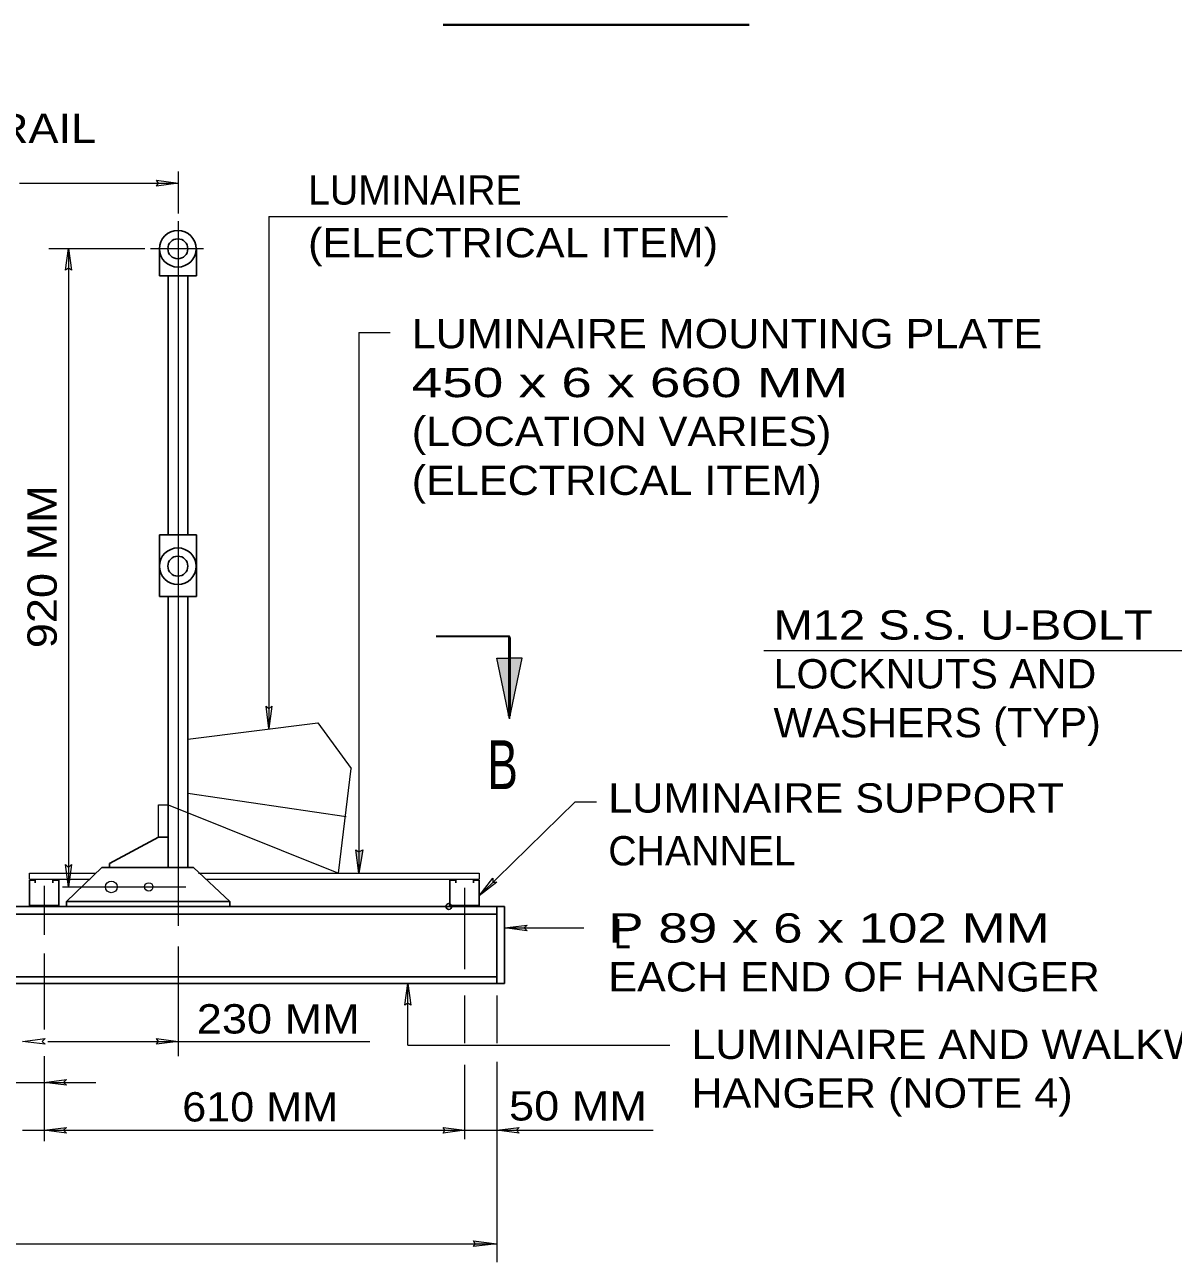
# Model space of a CAD drawing. Extents: x 312601.858 to 312602.699, y 144420.109 to 144420.704.
# Drawn here: x 312602.0438 to 312602.1613, y 144420.4578 to 144420.5844 of the extents above; entities that cross this region are included whole.
import ezdxf
from ezdxf.enums import TextEntityAlignment as Align

# ---------------------------------------------------------------- set-up
doc = ezdxf.new("R2010")
doc.units = 0
doc.header["$LTSCALE"] = 0.0012
doc.header["$PDMODE"] = 32
doc.header["$PDSIZE"] = 0.0006
doc.linetypes.add('DOT_DASHED', pattern=[7.7, 5, -1.2, 0.3, -1.2])
doc.linetypes.add('LONG_DASHED', pattern=[7.5, 6, -1.5])
for name, color, linetype, lineweight in [('1', 7, 'Continuous', 13), ('2', 7, 'Continuous', 13), ('39', 7, 'Continuous', 13), ('5', 7, 'Continuous', 25)]:
    doc.layers.add(name, color=color, linetype=linetype, lineweight=lineweight)

msp = doc.modelspace()

# ---------------------------------------------------------------- hatches: boundary and pattern name
at = {"layer": '1'}
for points in [[(312602.0921, 144420.5196), (312602.0934, 144420.5196), (312602.0934, 144420.5134)], [(312602.0921, 144420.5196), (312602.0934, 144420.5196), (312602.0934, 144420.5134)], [(312602.0947, 144420.5196), (312602.0934, 144420.5196), (312602.0934, 144420.5134)], [(312602.0947, 144420.5196), (312602.0934, 144420.5196), (312602.0934, 144420.5134)]]:
    msp.add_hatch(color=256, dxfattribs=at).paths.add_polyline_path(points)
at = {"layer": '39'}
for points in [[(312602.078, 144420.4998), (312602.0784, 144420.5), (312602.078, 144420.4976), (312602.0777, 144420.5)], [(312602.0899, 144420.4597), (312602.0897, 144420.46), (312602.0921, 144420.4597), (312602.0897, 144420.4594)]]:
    msp.add_hatch(color=256, dxfattribs=at).paths.add_polyline_path(points)

# ---------------------------------------------------------------- linework, layer by layer
at = {"layer": '1'}
for p, q in [((312602.0595, 144420.5694), (312602.0595, 144420.5651)), ((312602.0433, 144420.5682), (312602.0595, 144420.5682)), ((312602.0688, 144420.5648), (312602.1157, 144420.5648)), ((312602.0688, 144420.5648), (312602.0688, 144420.5124)), ((312602.0463, 144420.5615), (312602.0561, 144420.5615)), ((312602.0483, 144420.5615), (312602.0483, 144420.4962)), ((312602.078, 144420.5529), (312602.078, 144420.4976)), ((312602.078, 144420.5529), (312602.0812, 144420.5529)), ((312602.0935, 144420.5137), (312602.0935, 144420.5217)), ((312602.1194, 144420.5204), (312602.1734, 144420.5204)), ((312602.0903, 144420.4976), (312602.0903, 144420.497)), ((312602.0477, 144420.4962), (312602.0603, 144420.4962)), ((312602.0929, 144420.492), (312602.101, 144420.492)), ((312602.0595, 144420.4901), (312602.0595, 144420.4789)), ((312602.0458, 144420.4894), (312602.0458, 144420.4816)), ((312602.083, 144420.48), (312602.083, 144420.4863)), ((312602.0921, 144420.4851), (312602.0921, 144420.4802)), ((312602.0462, 144420.4804), (312602.0791, 144420.4804)), ((312602.083, 144420.48), (312602.1098, 144420.48)), ((312602.0458, 144420.4789), (312602.0458, 144420.4702)), ((312602.0921, 144420.4783), (312602.0921, 144420.4578)), ((312602.0888, 144420.478), (312602.0888, 144420.4704)), ((312602.0436, 144420.4713), (312602.0888, 144420.4713)), ((312601.967, 144420.4597), (312602.0921, 144420.4597))]:
    msp.add_line(p, q, dxfattribs=at)
at = {"layer": '1', "linetype": 'DOT_DASHED'}
for p, q in [((312602.0595, 144420.5643), (312602.0595, 144420.4922)), ((312602.0567, 144420.5615), (312602.0621, 144420.5615)), ((312602.0458, 144420.4963), (312602.0458, 144420.4913)), ((312602.0888, 144420.4961), (312602.0888, 144420.4878)), ((312602.0888, 144420.4851), (312602.0888, 144420.4802))]:
    msp.add_line(p, q, dxfattribs=at)
at = {"layer": '1', "lineweight": 25}
for p, q in [((312602.0576, 144420.5615), (312602.0576, 144420.5587)), ((312602.0614, 144420.5615), (312602.0614, 144420.5587)), ((312602.0576, 144420.5587), (312602.0614, 144420.5587)), ((312602.0585, 144420.5587), (312602.0585, 144420.5322)), ((312602.0605, 144420.5587), (312602.0605, 144420.5322)), ((312602.0576, 144420.5322), (312602.0614, 144420.5322)), ((312602.0576, 144420.5322), (312602.0576, 144420.5259)), ((312602.0614, 144420.5322), (312602.0614, 144420.5259)), ((312602.0576, 144420.5259), (312602.0614, 144420.5259)), ((312602.0585, 144420.5259), (312602.0585, 144420.4982)), ((312602.0605, 144420.5259), (312602.0605, 144420.4982)), ((312602.0525, 144420.4986), (312602.0575, 144420.5013)), ((312602.0575, 144420.5013), (312602.0585, 144420.5013)), ((312602.0525, 144420.4986), (312602.0525, 144420.4982)), ((312602.0517, 144420.4982), (312602.0481, 144420.4947)), ((312602.0517, 144420.4982), (312602.0611, 144420.4982)), ((312602.0648, 144420.4947), (312602.0611, 144420.4982)), ((312602.0481, 144420.4942), (312602.0481, 144420.4947)), ((312602.0481, 144420.4947), (312602.0648, 144420.4947)), ((312602.0648, 144420.4947), (312602.0648, 144420.4942)), ((312601.967, 144420.4934), (312602.0921, 144420.4934)), ((312601.9917, 144420.4942), (312602.0929, 144420.4942)), ((312602.0921, 144420.4942), (312602.0921, 144420.4863)), ((312602.0929, 144420.4942), (312602.0929, 144420.4863)), ((312602.0921, 144420.487), (312601.967, 144420.487)), ((312602.0929, 144420.4863), (312601.9662, 144420.4863))]:
    msp.add_line(p, q, dxfattribs=at)
at = {"layer": '1', "linetype": 'LONG_DASHED'}
for p, q in [((312602.0605, 144420.5113), (312602.0738, 144420.513)), ((312602.0738, 144420.513), (312602.0772, 144420.5083)), ((312602.0759, 144420.4976), (312602.0772, 144420.5083)), ((312602.0605, 144420.5058), (312602.0767, 144420.5034)), ((312602.0575, 144420.5013), (312602.0575, 144420.5046)), ((312602.0443, 144420.4976), (312602.0511, 144420.4976)), ((312602.0616, 144420.4976), (312602.0903, 144420.4976)), ((312602.0443, 144420.497), (312602.0505, 144420.497)), ((312602.0624, 144420.497), (312602.0903, 144420.497))]:
    msp.add_line(p, q, dxfattribs=at)
at = {"layer": '1'}
for points in [[(312602.0573, 144420.5685), (312602.0595, 144420.5682), (312602.0573, 144420.5679), (312602.0575, 144420.5682)], [(312602.048, 144420.5593), (312602.0483, 144420.5615), (312602.0486, 144420.5593), (312602.0483, 144420.5595)], [(312602.0921, 144420.5196), (312602.0934, 144420.5196), (312602.0934, 144420.5134)], [(312602.0921, 144420.5196), (312602.0934, 144420.5196), (312602.0934, 144420.5134)], [(312602.0947, 144420.5196), (312602.0934, 144420.5196), (312602.0934, 144420.5134)], [(312602.0947, 144420.5196), (312602.0934, 144420.5196), (312602.0934, 144420.5134)], [(312602.0691, 144420.5147), (312602.0688, 144420.5124), (312602.0685, 144420.5147), (312602.0688, 144420.5144)], [(312602.0486, 144420.4985), (312602.0483, 144420.4962), (312602.048, 144420.4985), (312602.0483, 144420.4982)], [(312602.0921, 144420.4967), (312602.0903, 144420.4953), (312602.0917, 144420.4971), (312602.0917, 144420.4967)], [(312602.0952, 144420.4917), (312602.0929, 144420.492), (312602.0952, 144420.4923), (312602.0949, 144420.492)], [(312602.0827, 144420.4841), (312602.083, 144420.4863), (312602.0833, 144420.4841), (312602.083, 144420.4843)], [(312602.0459, 144420.4801), (312602.0436, 144420.4804), (312602.0459, 144420.4807), (312602.0456, 144420.4804)], [(312602.0573, 144420.4807), (312602.0595, 144420.4804), (312602.0573, 144420.4801), (312602.0575, 144420.4804)], [(312602.0481, 144420.4759), (312602.0458, 144420.4762), (312602.0481, 144420.4765), (312602.0478, 144420.4762)], [(312602.0481, 144420.471), (312602.0458, 144420.4713), (312602.0481, 144420.4716), (312602.0478, 144420.4713)], [(312602.0866, 144420.4716), (312602.0888, 144420.4713), (312602.0866, 144420.471), (312602.0868, 144420.4713)], [(312602.0944, 144420.471), (312602.0921, 144420.4713), (312602.0944, 144420.4716), (312602.0941, 144420.4713)]]:
    msp.add_lwpolyline(points, close=True, dxfattribs=at)
at = {"layer": '1', "lineweight": 35}
msp.add_lwpolyline([(312602.0934, 144420.5196), (312602.0934, 144420.5218), (312602.0859, 144420.5218)], dxfattribs=at)
msp.add_lwpolyline([(312602.0934, 144420.5196), (312602.0934, 144420.5218), (312602.0859, 144420.5218)], dxfattribs=at)
at = {"layer": '1'}
for points in [[(312602.0933, 144420.5219), (312602.0933, 144420.5137), (312602.0935, 144420.5217)], [(312602.0905, 144420.4955), (312602.1001, 144420.5049), (312602.1023, 144420.5049)], [(312602.0268, 144420.4762), (312602.0436, 144420.4762), (312602.0458, 144420.4762), (312602.0511, 144420.4762)], [(312602.0888, 144420.4713), (312602.0921, 144420.4713), (312602.1081, 144420.4713)]]:
    msp.add_lwpolyline(points, dxfattribs=at)
at = {"layer": '1', "linetype": 'LONG_DASHED'}
msp.add_lwpolyline([(312602.0575, 144420.5046), (312602.0585, 144420.5046), (312602.0759, 144420.4976)], dxfattribs=at)
at = {"layer": '1', "lineweight": 25}
for centre, radius in [((312602.05948, 144420.56148), 0.00187), ((312602.05948, 144420.56148), 0.00102), ((312602.05948, 144420.52901), 0.00187), ((312602.05948, 144420.52901), 0.00102)]:
    msp.add_circle(centre, radius, dxfattribs=at)
at = {"layer": '1'}
for centre, radius in [((312602.05268, 144420.4962), 0.000595), ((312602.056505, 144420.4962), 0.000425)]:
    msp.add_circle(centre, radius, dxfattribs=at)
at = {"layer": '2', "lineweight": 40}
msp.add_line((312602.0866, 144420.5844), (312602.1179, 144420.5844), dxfattribs=at)
at = {"layer": '39'}
for points in [[(312602.078, 144420.4998), (312602.0784, 144420.5), (312602.078, 144420.4976), (312602.0777, 144420.5)], [(312602.0899, 144420.4597), (312602.0897, 144420.46), (312602.0921, 144420.4597), (312602.0897, 144420.4594)]]:
    msp.add_lwpolyline(points, close=True, dxfattribs=at)
at = {"layer": '5', "lineweight": 13}
for p, q in [((312602.0443, 144420.497), (312602.0443, 144420.4976)), ((312602.0872, 144420.4942), (312602.0873, 144420.4942))]:
    msp.add_line(p, q, dxfattribs=at)
at = {"layer": '5'}
for p, q in [((312602.0443, 144420.4969), (312602.0443, 144420.4943)), ((312602.0473, 144420.4943), (312602.0473, 144420.4969)), ((312602.0873, 144420.4969), (312602.0873, 144420.4943)), ((312602.0903, 144420.4943), (312602.0903, 144420.4969)), ((312602.0443, 144420.4943), (312602.0473, 144420.4943)), ((312602.0873, 144420.4943), (312602.0903, 144420.4943))]:
    msp.add_line(p, q, dxfattribs=at)
for points in [[(312602.0449, 144420.4966), (312602.0449, 144420.4969), (312602.0443, 144420.4969)], [(312602.0473, 144420.4969), (312602.0467, 144420.4969), (312602.0467, 144420.4966)], [(312602.0879, 144420.4966), (312602.0879, 144420.4969), (312602.0873, 144420.4969)], [(312602.0903, 144420.4969), (312602.0897, 144420.4969), (312602.0897, 144420.4966)]]:
    msp.add_lwpolyline(points, dxfattribs=at)
msp.add_point((312602.0872, 144420.4942), dxfattribs=at)

# ---------------------------------------------------------------- texts
at = {"layer": '2'}
for s, width, p in [('C OF HANDRAIL ', 1.15, (312602.0155, 144420.5723)), ('(ELECTRICAL ITEM)', 1.1, (312602.0728, 144420.5606)), ('LUMINAIRE MOUNTING PLATE', 1.1, (312602.0834, 144420.5513)), ('450 x 6 x 660 MM', 1.4, (312602.0834, 144420.5463)), ('(LOCATION VARIES)', 1.1, (312602.0834, 144420.5413)), ('(ELECTRICAL ITEM)', 1.1, (312602.0834, 144420.5363)), ('M12 S.S. U-BOLT', 1.2, (312602.1204, 144420.5215)), ('LOCKNUTS AND', 1.05, (312602.1204, 144420.5165)), ('WASHERS (TYP)', 1.05, (312602.1204, 144420.5115)), ('LUMINAIRE SUPPORT', 1.1, (312602.1035, 144420.5038)), ('P 89 x 6 x 102 MM', 1.35, (312602.1035, 144420.4905)), ('EACH END OF HANGER ', 1.1, (312602.1035, 144420.4855)), ('LUMINAIRE AND WALKWAY', 1.1, (312602.112, 144420.4786)), ('HANGER (NOTE 4)', 1.1, (312602.112, 144420.4736))]:
    msp.add_text(s, height=0.003, dxfattribs=dict(at, width=width)).set_placement(p)
for s, p in [('LUMINAIRE', (312602.0728, 144420.566)), ('CHANNEL', (312602.1035, 144420.4984))]:
    msp.add_text(s, height=0.003, dxfattribs=at).set_placement(p)
at = {"layer": '2', "width": 1.15}
msp.add_text('920 MM', height=0.003, rotation=90, dxfattribs=at).set_placement((312602.0471, 144420.52895), align=Align.CENTER)
at = {"layer": '2'}
for s, height, width, p in [('B', 0.005, 0.7, (312602.0927, 144420.5062)), ('L', 0.003, 0.75, (312602.10495, 144420.4899)), ('230 MM', 0.003, 1.15, (312602.06975, 144420.4812)), ('610 MM', 0.003, 1.1, (312602.0679, 144420.4722)), ('50 MM', 0.003, 1.15, (312602.1004, 144420.4723))]:
    msp.add_text(s, height=height, dxfattribs=dict(at, width=width)).set_placement(p, align=Align.CENTER)

doc.saveas('drawing.dxf')
